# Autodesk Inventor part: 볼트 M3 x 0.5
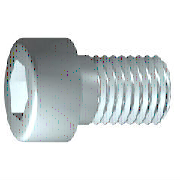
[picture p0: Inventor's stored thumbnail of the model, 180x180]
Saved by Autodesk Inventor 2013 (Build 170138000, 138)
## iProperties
IsCustomPart: 1
Company: 한국ATC센터
Created: 2015-12
Part Number: 볼트 M3 x 0.5
Material: 스테인리스강
Description: 6각머리 태핑 나사
Document SubType Name: Modeling
Standard: KS B 1003
Designer: mdu
Standards Organization: KS
Language: ko-KR
Size Designation: M 4 x 12
Categories: <MemberInstance><Categories><Category DisplayName="조임쇠" InternalName="e4da775c-781d-43d5-af7c-5136215cf5a6" Mnemonic="FSTN"><Category DisplayName="볼트" InternalN
Density: 8.08 g/cm^3
Mass: 1.41278 g
Surface Area: 2.584 cm^2
Volume: 0.174849 cm^3
Author: mdu
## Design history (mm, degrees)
sketch "스케치1"
  geometry: L1 (-0.867, 0)-(15, 0); L2 (15, 0)-(15, 1.5); L3 (15, 1.5)-(1.25, 1.5); L4 (1.25, 1.5)-(0.943, 1.5); L5 (0.943, 1.5)-(0, 1.5); L6 (0, 1.5)-(0, 2.75); L7 (0, 2.75)-(-3, 2.75); L8 (-3, 2.75)-(-3, 1.443); L9 (-3, 1.443)-(-1.7, 1.443); L10 (-1.7, 1.443)-(-0.867, 0); L11 (-6.6, 0)-(18.6, 0) reference; L12 (0, -0.55)-(0, 3.3) reference; L13 (1.25, 1.5)-(0, 1.5)
  constraints: 22 end point, 6 parallel, 2 collinear, 2 perpendicular, 1 horizontal, 1 point on line
  dimensions: "d1" = 13.75 distance from line of L3.end L2 (= GEL); "d2" = 0.30683 distance of L4.end L3.end (computed from GAL); "d3" = 3 distance between parallel lines of L8 L6 (= KOH); "d4" = 1.3 distance of L8.end L9.end (= INTI); "d5" = 60 deg angle of L10 L1; "d6" = 3 diameter of L3 L1 (= GD); "d7" = 3 diameter of L5 L1 (= BDM); "d8" = 2.88675 diameter of L9 L1 (= 1.1547 x SW); "d9" = 5.5 diameter of L7 L1 (= KOD); "d26" = 15 distance between parallel lines of L12 L2 (= NLG)
revolve "본체" sketch "스케치1" stored, may be unused: angle "d10" = 90 deg
sketch "스케치2"
  geometry: L1 (0, -3.85)-(0, 3.85) reference; L2 (-3.85, 0)-(3.85, 0) reference; L3 (1.443, 0)-(0.722, -1.25); L4 (0.722, -1.25)-(-0.722, -1.25); L5 (-0.722, -1.25)-(-1.443, 0); L6 (-1.443, 0)-(-0.722, 1.25); L7 (-0.722, 1.25)-(0.722, 1.25); L8 (0.722, 1.25)-(1.443, 0); 2 further points
  constraints: 12 end point, 1 coincident, 1 horizontal alignment, 1 point on line, 12 other
extrude "슬롯" join sketch "스케치2" stored distance "d11" = 10; taper "d12" = 0 deg
workplane "Work Plane1"
fillet "Fillet2" dims "d30" = 0.1 (= R)
body "Solid1"
fillet "모깎기1" dims "d17" = 0.3 (= RR)
feature "스레드" dims "d13" = 13.75 (= GEL), "d14" = 0
chamfer "모따기1" distance "d15" = 0.30673 (= -0.5 x SPD + 0.5 x GD); stored, may be unused: second distance "d16" = 0.30673 (= GUL), angle "d27" = 45 deg
other parameters: "GD" = 3 (= NND) [user parameter; used in 2 equation terms], "NLG" = 15 [user parameter; used in 1 equation term], "GEL" = 13.75 [user parameter; used in 2 equation terms], "KOD" = 5.5 [user parameter; used in 1 equation term], "KOH" = 3 [user parameter; used in 1 equation term], "INTI" = 1.3 [user parameter; used in 1 equation term], "GAL" = 0.30673 (= 0.61345 x PTC) [user parameter; used in 1 equation term], "GUL" = 0.30673 (= 0.61345 x PTC) [user parameter; used in 1 equation term], "BDM" = 3 (= NND) [user parameter; used in 1 equation term], "SW" = 2.5 [user parameter; used in 2 equation terms], "RR" = 0.3 [user parameter; used in 1 equation term], "SPD" = 2.38655 (= NND - 1.2269 x PTC) [user parameter; used in 1 equation term], "d19" = 0, "d28" = 0, "d29" = 0, "R" = 0.1 [user parameter; used in 1 equation term], "PHH" = 0.1 [user parameter], "GD1" = 2.38655 (= THREADDIA - 1.2269 x PTC) [user parameter], "THREADDIA" = 3 [user parameter; used in 1 equation term], "FAWI" = 45 deg [user parameter], "PTC" = 0.5 [user parameter; used in 5 equation terms], "NND" = 3 [user parameter; used in 3 equation terms], "TOA" = 30 deg [user parameter], "E0" = 2.8875 (= 1.155 x SW) [user parameter]
